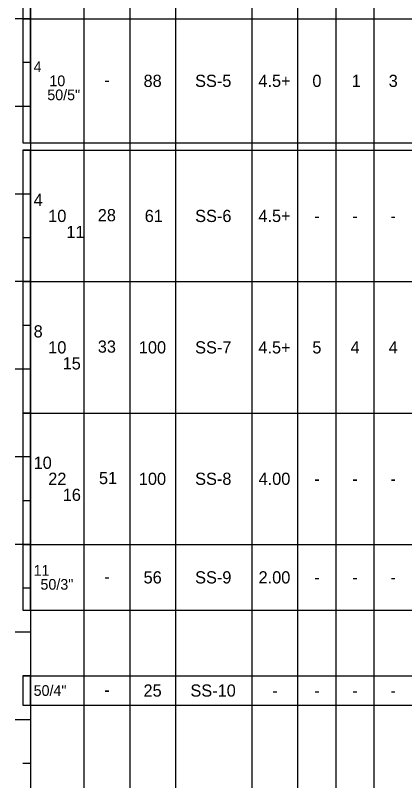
# Model space of a CAD drawing. Extents: x 0 to 0.83, y -0.65 to 1.27.
# Drawn here: x 0.4042 to 0.6168, y 0.4451 to 0.8629 of the extents above; entities that cross this region are included whole.
import ezdxf

# ---------------------------------------------------------------- set-up
doc = ezdxf.new("R2010")
doc.units = 0

msp = doc.modelspace()

# ---------------------------------------------------------------- linework, layer by layer
for points in [[(0.4125, 1.22083), (0.4125, -0.64575)], [(0.4125, 1.22083), (0.4125, -0.64575)], [(0.44167, 1.22083), (0.44167, -0.64575)], [(0.46667, 1.22083), (0.46667, -0.64575)], [(0.49167, 1.22083), (0.49167, -0.64575)], [(0.53333, 1.22083), (0.53333, -0.64575)], [(0.55833, 1.22083), (0.55833, -0.64575)], [(0.57917, 1.20833), (0.57917, -0.64575)], [(0.6, 1.20833), (0.6, -0.64575)], [(0.40833, 0.93275), (0.40833, 0.861)], [(0.4125, 0.861), (0.40417, 0.861)], [(0.40833, 0.861), (0.4125, 0.861)], [(0.40833, 0.861), (0.40833, 0.79323)], [(0.40833, 0.861), (0.4125, 0.861)], [(0.4125, 0.861), (0.40833, 0.861)], [(0.4125, 0.861), (0.44167, 0.861)], [(0.44167, 0.861), (0.46667, 0.861)], [(0.46667, 0.861), (0.49167, 0.861)], [(0.49167, 0.861), (0.53333, 0.861)], [(0.53333, 0.861), (0.55833, 0.861)], [(0.55833, 0.861), (0.57917, 0.861)], [(0.57917, 0.861), (0.6, 0.861)], [(0.6, 0.861), (0.62083, 0.861)], [(0.4125, 0.83708), (0.40833, 0.83708)], [(0.4125, 0.81317), (0.40417, 0.81317)], [(0.4125, 0.81317), (0.40833, 0.81317)], [(0.40833, 0.79323), (0.4125, 0.79323)], [(0.4125, 0.79323), (0.44167, 0.79323)], [(0.44167, 0.79323), (0.46667, 0.79323)], [(0.46667, 0.79323), (0.49167, 0.79323)], [(0.49167, 0.79323), (0.53333, 0.79323)], [(0.53333, 0.79323), (0.55833, 0.79323)], [(0.55833, 0.79323), (0.57917, 0.79323)], [(0.57917, 0.79323), (0.6, 0.79323)], [(0.6, 0.79323), (0.62083, 0.79323)], [(0.40833, 0.78925), (0.40833, 0.7175)], [(0.40833, 0.78925), (0.4125, 0.78925)], [(0.4125, 0.78925), (0.40833, 0.78925)], [(0.4125, 0.78925), (0.44167, 0.78925)], [(0.44167, 0.78925), (0.46667, 0.78925)], [(0.46667, 0.78925), (0.49167, 0.78925)], [(0.49167, 0.78925), (0.53333, 0.78925)], [(0.53333, 0.78925), (0.55833, 0.78925)], [(0.55833, 0.78925), (0.57917, 0.78925)], [(0.57917, 0.78925), (0.6, 0.78925)], [(0.6, 0.78925), (0.62083, 0.78925)], [(0.4125, 0.76533), (0.40417, 0.76533)], [(0.4125, 0.76533), (0.40833, 0.76533)], [(0.4125, 0.74142), (0.40833, 0.74142)], [(0.4125, 0.7175), (0.40417, 0.7175)], [(0.40833, 0.7175), (0.4125, 0.7175)], [(0.40833, 0.7175), (0.40833, 0.64575)], [(0.40833, 0.7175), (0.4125, 0.7175)], [(0.4125, 0.7175), (0.40833, 0.7175)], [(0.4125, 0.7175), (0.44167, 0.7175)], [(0.44167, 0.7175), (0.46667, 0.7175)], [(0.46667, 0.7175), (0.49167, 0.7175)], [(0.49167, 0.7175), (0.53333, 0.7175)], [(0.53333, 0.7175), (0.55833, 0.7175)], [(0.55833, 0.7175), (0.57917, 0.7175)], [(0.57917, 0.7175), (0.6, 0.7175)], [(0.6, 0.7175), (0.62083, 0.7175)], [(0.4125, 0.69358), (0.40833, 0.69358)], [(0.4125, 0.66967), (0.40417, 0.66967)], [(0.4125, 0.66967), (0.40833, 0.66967)], [(0.40833, 0.64575), (0.4125, 0.64575)], [(0.40833, 0.64575), (0.40833, 0.574)], [(0.40833, 0.64575), (0.4125, 0.64575)], [(0.4125, 0.64575), (0.40833, 0.64575)], [(0.4125, 0.64575), (0.44167, 0.64575)], [(0.44167, 0.64575), (0.46667, 0.64575)], [(0.46667, 0.64575), (0.49167, 0.64575)], [(0.49167, 0.64575), (0.53333, 0.64575)], [(0.53333, 0.64575), (0.55833, 0.64575)], [(0.55833, 0.64575), (0.57917, 0.64575)], [(0.57917, 0.64575), (0.6, 0.64575)], [(0.6, 0.64575), (0.62083, 0.64575)], [(0.4125, 0.62183), (0.40417, 0.62183)], [(0.4125, 0.62183), (0.40833, 0.62183)], [(0.4125, 0.59792), (0.40833, 0.59792)], [(0.4125, 0.574), (0.40417, 0.574)], [(0.40833, 0.574), (0.4125, 0.574)], [(0.40833, 0.574), (0.40833, 0.53812)], [(0.40833, 0.574), (0.4125, 0.574)], [(0.4125, 0.574), (0.40833, 0.574)], [(0.4125, 0.574), (0.44167, 0.574)], [(0.44167, 0.574), (0.46667, 0.574)], [(0.46667, 0.574), (0.49167, 0.574)], [(0.49167, 0.574), (0.53333, 0.574)], [(0.53333, 0.574), (0.55833, 0.574)], [(0.55833, 0.574), (0.57917, 0.574)], [(0.57917, 0.574), (0.6, 0.574)], [(0.6, 0.574), (0.62083, 0.574)], [(0.4125, 0.55008), (0.40833, 0.55008)], [(0.40833, 0.53812), (0.4125, 0.53812)], [(0.4125, 0.53812), (0.44167, 0.53812)], [(0.44167, 0.53812), (0.46667, 0.53812)], [(0.46667, 0.53812), (0.49167, 0.53812)], [(0.49167, 0.53812), (0.53333, 0.53812)], [(0.53333, 0.53812), (0.55833, 0.53812)], [(0.55833, 0.53812), (0.57917, 0.53812)], [(0.57917, 0.53812), (0.6, 0.53812)], [(0.6, 0.53812), (0.62083, 0.53812)], [(0.4125, 0.52617), (0.40417, 0.52617)], [(0.4125, 0.52617), (0.40833, 0.52617)], [(0.40833, 0.50225), (0.40833, 0.4863)], [(0.40833, 0.50225), (0.4125, 0.50225)], [(0.4125, 0.50225), (0.40833, 0.50225)], [(0.4125, 0.50225), (0.44167, 0.50225)], [(0.44167, 0.50225), (0.46667, 0.50225)], [(0.46667, 0.50225), (0.49167, 0.50225)], [(0.49167, 0.50225), (0.53333, 0.50225)], [(0.53333, 0.50225), (0.55833, 0.50225)], [(0.55833, 0.50225), (0.57917, 0.50225)], [(0.57917, 0.50225), (0.6, 0.50225)], [(0.6, 0.50225), (0.62083, 0.50225)], [(0.40833, 0.4863), (0.4125, 0.4863)], [(0.4125, 0.4863), (0.44167, 0.4863)], [(0.44167, 0.4863), (0.46667, 0.4863)], [(0.46667, 0.4863), (0.49167, 0.4863)], [(0.49167, 0.4863), (0.53333, 0.4863)], [(0.53333, 0.4863), (0.55833, 0.4863)], [(0.55833, 0.4863), (0.57917, 0.4863)], [(0.57917, 0.4863), (0.6, 0.4863)], [(0.6, 0.4863), (0.62083, 0.4863)], [(0.4125, 0.47833), (0.40417, 0.47833)], [(0.4125, 0.47833), (0.40833, 0.47833)], [(0.4125, 0.45442), (0.40833, 0.45442)]]:
    msp.add_lwpolyline(points)
for points in [[(0.40833, 0.861), (0.4125, 0.861), (0.4125, 0.93275), (0.40833, 0.93275)], [(0.40833, 0.79323), (0.4125, 0.79323), (0.4125, 0.861), (0.40833, 0.861)], [(0.40833, 0.7175), (0.4125, 0.7175), (0.4125, 0.78925), (0.40833, 0.78925)], [(0.40833, 0.64575), (0.4125, 0.64575), (0.4125, 0.7175), (0.40833, 0.7175)], [(0.40833, 0.574), (0.4125, 0.574), (0.4125, 0.64575), (0.40833, 0.64575)], [(0.40833, 0.53812), (0.4125, 0.53812), (0.4125, 0.574), (0.40833, 0.574)], [(0.40833, 0.4863), (0.4125, 0.4863), (0.4125, 0.50225), (0.40833, 0.50225)]]:
    msp.add_lwpolyline(points, close=True)

# ---------------------------------------------------------------- texts
for s, height, p in [('4', 0.00583, (0.41417, 0.83186)), ('10', 0.005833, (0.42275, 0.8242)), ('88', 0.006667, (0.47419, 0.82378)), ('SS-5', 0.006667, (0.50233, 0.82378)), ('4.5+', 0.006667, (0.5369, 0.82378)), ('0', 0.00667, (0.56638, 0.82378)), ('1', 0.00667, (0.58785, 0.82378)), ('3', 0.00667, (0.60804, 0.82378)), ('-', 0.00667, (0.45276, 0.8242)), ('50/5"', 0.005833, (0.42163, 0.81654)), ('4', 0.00667, (0.41417, 0.75879)), ('10', 0.006667, (0.42213, 0.75004)), ('28', 0.006667, (0.44919, 0.75046)), ('61', 0.006667, (0.47484, 0.75004)), ('SS-6', 0.006667, (0.50236, 0.75004)), ('4.5+', 0.006667, (0.5369, 0.75004)), ('-', 0.00667, (0.56734, 0.75004)), ('-', 0.00667, (0.58818, 0.75004)), ('-', 0.00667, (0.60901, 0.75004)), ('11', 0.006667, (0.43205, 0.74129)), ('8', 0.00667, (0.41417, 0.68704)), ('33', 0.006667, (0.4492, 0.67871)), ('10', 0.006667, (0.42213, 0.67829)), ('100', 0.006667, (0.47162, 0.67829)), ('SS-7', 0.006667, (0.50236, 0.67829)), ('4.5+', 0.006667, (0.5369, 0.67829)), ('5', 0.00667, (0.56635, 0.67829)), ('4', 0.00667, (0.58722, 0.67829)), ('4', 0.00667, (0.60805, 0.67829)), ('15', 0.006667, (0.43001, 0.66954)), ('10', 0.006667, (0.41417, 0.61529)), ('22', 0.006667, (0.42215, 0.60654)), ('51', 0.006667, (0.44984, 0.60696)), ('100', 0.006667, (0.47162, 0.60654)), ('SS-8', 0.006667, (0.50235, 0.60654)), ('4.00', 0.006667, (0.537, 0.60654)), ('-', 0.00667, (0.56734, 0.60654)), ('-', 0.00667, (0.58818, 0.60654)), ('-', 0.00667, (0.60901, 0.60654)), ('16', 0.006667, (0.43007, 0.59779)), ('11', 0.005833, (0.41417, 0.55697)), ('-', 0.00667, (0.45276, 0.55314)), ('56', 0.006667, (0.4742, 0.55273)), ('SS-9', 0.006667, (0.50235, 0.55273)), ('2.00', 0.006667, (0.537, 0.55273)), ('50/3"', 0.005833, (0.4179, 0.54932)), ('-', 0.00667, (0.56734, 0.55273)), ('-', 0.00667, (0.58818, 0.55273)), ('-', 0.00667, (0.60901, 0.55273)), ('50/4"', 0.005833, (0.41417, 0.49136)), ('25', 0.006667, (0.47417, 0.49094)), ('SS-10', 0.006667, (0.49978, 0.49094)), ('-', 0.00667, (0.45276, 0.49136)), ('-', 0.00667, (0.54443, 0.49094)), ('-', 0.00667, (0.56734, 0.49094)), ('-', 0.00667, (0.58818, 0.49094)), ('-', 0.00667, (0.60901, 0.49094))]:
    msp.add_text(s, height=height).set_placement(p)

doc.saveas('drawing.dxf')
